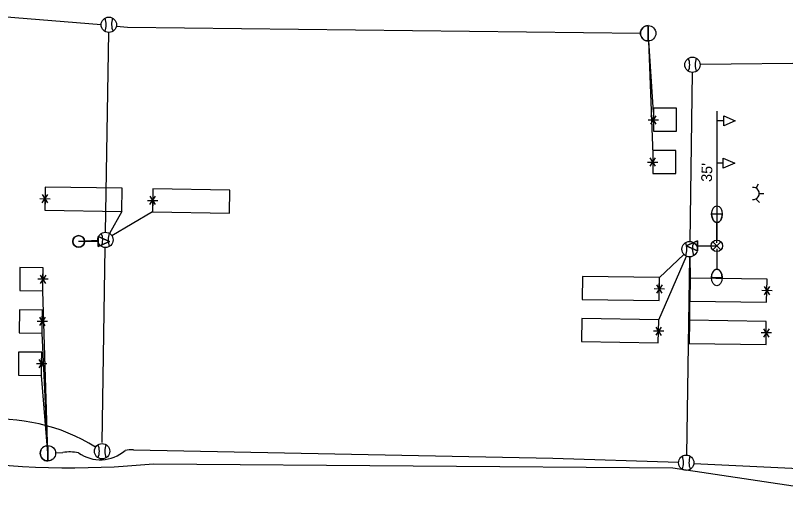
# Model space of a CAD drawing. Extents: x 596176 to 605330, y 332416 to 402398.
# Drawn here: x 602723.5 to 602923.8, y 366066.6 to 366192.6 of the extents above; entities that cross this region are included whole.
import ezdxf

# ---------------------------------------------------------------- set-up
doc = ezdxf.new("R2010")
doc.units = 0
for name, color, linetype in [('P_LTG', 7, 'Continuous'), ('P_SIG', 7, 'Continuous'), ('P_SIG_Bold', 7, 'Continuous'), ('P_SIG_Conduit', 7, 'Continuous'), ('P_SIG_IC', 7, 'Continuous'), ('P_SIG_Loops', 7, 'Continuous')]:
    doc.layers.add(name, color=color, linetype=linetype)

# ---------------------------------------------------------------- blocks, each defined once
blk = doc.blocks.new('_U303')
at = {"layer": 'P_LTG'}
for p, q in [((4.32, 25.12), (-4.14, 25.12)), ((0.05, 2.3), (0.05, 18.44))]:
    blk.add_line(p, q, dxfattribs=at)
blk.add_ellipse((0.09, 25.12), major_axis=(0, 6.65), ratio=0.636439, dxfattribs=at)
blk.add_ellipse((0.09, 25.12), major_axis=(0, 6.65), ratio=0.636439, start_param=1.570796, end_param=4.712389, dxfattribs=at)

msp = doc.modelspace()

# ---------------------------------------------------------------- linework, layer by layer
at = {"layer": 'P_SIG'}
for p, q in [((602888.02, 366189.97), (602888, 366185.97)), ((602907.65, 366165.18), (602905.88, 366165.18)), ((602907.56, 366154.18), (602905.79, 366154.18)), ((602916.08, 366147.68), (602916.68, 366148.76)), ((602916.05, 366144.89), (602916.93, 366143.9)), ((602916.9, 366146.31), (602918.13, 366146.31)), ((602744.98, 366133.79), (602739.92, 366133.8)), ((602900.82, 366132.69), (602905.88, 366132.67)), ((602731.95, 366080.67), (602731.93, 366076.67))]:
    msp.add_line(p, q, dxfattribs=at)
for points in [[(602888, 366185.97), (602888.02, 366189.97)], [(602747.94, 366133.79), (602744.98, 366132.47), (602744.98, 366135.11), (602747.94, 366133.79)], [(602744.98, 366132.47), (602747.94, 366133.79), (602744.98, 366135.11), (602744.98, 366132.47)], [(602897.86, 366132.69), (602900.82, 366134), (602900.82, 366131.37), (602897.86, 366132.69)], [(602897.86, 366132.69), (602900.82, 366134), (602900.82, 366131.37), (602897.86, 366132.69)], [(602900.82, 366134), (602897.86, 366132.69), (602900.82, 366131.37), (602900.82, 366134)], [(602731.93, 366076.67), (602731.95, 366080.67)]]:
    msp.add_lwpolyline(points, dxfattribs=at)
for points in [[(602910.61, 366165.18), (602907.65, 366163.86), (602907.65, 366166.49)], [(602910.52, 366154.18), (602907.56, 366152.86), (602907.56, 366155.49)]]:
    msp.add_lwpolyline(points, close=True, dxfattribs=at)
for centre, radius in [((602747.78, 366190.19), 2), ((602888.01, 366187.97), 2), ((602899.53, 366179.78), 2), ((602739.92, 366133.8), 1.52), ((602739.92, 366133.8), 1.52), ((602739.92, 366133.8), 1.52), ((602746.89, 366134.2), 2), ((602898.79, 366131.79), 2), ((602731.94, 366078.67), 2), ((602746.02, 366079.2), 2), ((602897.91, 366076.21), 2)]:
    msp.add_circle(centre, radius, dxfattribs=at)
for centre, radius, start, end in [((602742.71, 366190.22), 4.36, 336.6741, 22.5272), ((602752.85, 366190.23), 4.36, 157.5751, 203.4282), ((602888.01, 366187.97), 2, 89.7008, 180), ((602888.01, 366187.97), 2, 180, 269.7008), ((602894.46, 366179.82), 4.36, 336.6741, 22.5272), ((602904.6, 366179.83), 4.36, 157.5751, 203.4282), ((602915.32, 366146.3), 1.58, 262.2462, 97.7538), ((602739.92, 366133.8), 1.52, 0, 180), ((602741.82, 366134.23), 4.36, 336.6741, 22.5272), ((602751.96, 366134.24), 4.36, 157.5751, 203.4282), ((602739.92, 366133.8), 1.52, 180, 0), ((602893.72, 366131.82), 4.36, 336.6741, 22.5272), ((602903.86, 366131.83), 4.36, 157.5751, 203.4282), ((602731.94, 366078.67), 2, 89.7008, 180), ((602740.95, 366079.24), 4.36, 336.6741, 22.5272), ((602751.09, 366079.25), 4.36, 157.5751, 203.4282), ((602731.94, 366078.67), 2, 180, 269.7008), ((602892.84, 366076.24), 4.36, 336.6741, 22.5272), ((602902.98, 366076.25), 4.36, 157.5751, 203.4282)]:
    msp.add_arc(centre, radius, start, end, dxfattribs=at)
at = {"layer": 'P_SIG_Bold'}
for p, q in [((602905.88, 366167.67), (602905.88, 366134.17)), ((602906.94, 366133.73), (602904.82, 366131.61)), ((602906.94, 366131.61), (602904.82, 366133.73))]:
    msp.add_line(p, q, dxfattribs=at)
msp.add_circle((602905.88, 366132.67), 1.5, dxfattribs=at)
at = {"layer": 'P_SIG_Conduit'}
for points in [[(602716.8, 366192.63), (602745.78, 366190.29)], [(602749.75, 366189.85), (602752.6, 366189.61), (602886.01, 366187.99)], [(602746.92, 366136.2), (602747.75, 366188.19)], [(602933.66, 366180.19), (602901.53, 366179.86)], [(602899.5, 366177.78), (602898.82, 366133.79)], [(602744.89, 366134.08), (602739.92, 366133.8)], [(602900.54, 366132.76), (602904.38, 366132.7)], [(602746.05, 366081.47), (602746.86, 366132.2)], [(602898.76, 366129.79), (602897.95, 366078.21)], [(602733.93, 366078.78), (602735.81, 366078.89)], [(602754.18, 366079.57), (602863.21, 366077.42), (602895.91, 366076.36)], [(602899.9, 366076.04), (602939.94, 366074.13)]]:
    msp.add_lwpolyline(points, dxfattribs=at)
for centre, radius, start, end in [((602719.11, 366039.94), 47.57, 57.9898, 96.3464), ((602737.54, 366066.77), 12.24, 79.0079, 98.1332), ((602745.55, 366086.8), 9.81, 234.6782, 311.0231), ((602753.8, 366070.72), 8.86, 87.5297, 101.8044)]:
    msp.add_arc(centre, radius, start, end, dxfattribs=at)
at = {"layer": 'P_SIG_IC'}
msp.add_lwpolyline([(602759.42, 366075.93), (602894.42, 366074.85), (602949.47, 366066.61)], dxfattribs=at)
msp.add_arc((602737.84, 366297.84), 222.95, 261.5069, 275.5534, dxfattribs=at)
at = {"layer": 'P_SIG_Loops'}
for p, q in [((602888.09, 366185.97), (602889.19, 366156.46)), ((602889.39, 366167.46), (602888.15, 366185.97)), ((602888.67, 366164.35), (602890.07, 366166.53)), ((602890.12, 366164.36), (602888.69, 366166.54)), ((602888.01, 366165.44), (602890.69, 366165.44)), ((602889.39, 366165.46), (602889.39, 366162.46)), ((602887.86, 366154.44), (602890.53, 366154.44)), ((602888.51, 366153.35), (602889.92, 366155.53)), ((602889.96, 366153.36), (602888.53, 366155.54)), ((602889.23, 366154.46), (602889.23, 366151.46)), ((602729.83, 366144.95), (602732.5, 366144.9)), ((602730.46, 366143.85), (602731.9, 366146)), ((602731.92, 366143.84), (602730.52, 366146.03)), ((602731.2, 366144.94), (602731.15, 366141.94)), ((602757.82, 366144.5), (602760.5, 366144.46)), ((602758.46, 366143.41), (602759.9, 366145.56)), ((602759.91, 366143.39), (602758.52, 366145.59)), ((602759.2, 366144.5), (602759.15, 366141.5)), ((602751.15, 366141.63), (602747.93, 366135.9)), ((602759.15, 366141.5), (602748.59, 366135.26)), ((602890.93, 366124.42), (602897.33, 366130.42)), ((602890.75, 366113.42), (602897.99, 366129.96)), ((602898.78, 366129.79), (602898.75, 366113.28)), ((602898.82, 366129.79), (602898.92, 366124.28)), ((602730.64, 366123.95), (602730.67, 366126.95)), ((602729.92, 366125.05), (602731.33, 366122.86)), ((602731.38, 366125.05), (602729.95, 366122.89)), ((602890.88, 366121.42), (602890.93, 366124.42)), ((602732.02, 366123.95), (602729.34, 366123.98)), ((602890.16, 366122.53), (602891.56, 366120.33)), ((602891.62, 366122.52), (602890.18, 366120.37)), ((602918.88, 366120.99), (602918.92, 366123.99)), ((602731.94, 366078.67), (602730.61, 366120.95)), ((602892.25, 366121.42), (602889.58, 366121.46)), ((602920.25, 366120.98), (602917.57, 366121.02)), ((602918.16, 366122.09), (602919.56, 366119.9)), ((602919.61, 366122.08), (602918.17, 366119.93)), ((602730.47, 366112.95), (602730.5, 366115.95)), ((602731.84, 366112.96), (602729.16, 366112.98)), ((602729.75, 366114.05), (602731.16, 366111.86)), ((602731.2, 366114.05), (602729.77, 366111.89)), ((602890.71, 366110.42), (602890.75, 366113.42)), ((602918.7, 366109.99), (602918.74, 366112.99)), ((602892.08, 366110.42), (602889.4, 366110.46)), ((602889.99, 366111.53), (602891.39, 366109.33)), ((602891.44, 366111.52), (602890, 366109.37)), ((602917.98, 366111.09), (602919.38, 366108.9)), ((602919.44, 366111.08), (602918, 366108.93)), ((602731.94, 366078.67), (602730.42, 366109.95)), ((602920.07, 366109.98), (602917.4, 366110.02)), ((602730.3, 366101.95), (602730.32, 366104.95)), ((602729.57, 366103.05), (602730.98, 366100.87)), ((602731.03, 366103.05), (602729.6, 366100.89)), ((602731.67, 366101.96), (602728.99, 366101.98)), ((602731.94, 366078.67), (602730.27, 366098.95))]:
    msp.add_line(p, q, dxfattribs=at)
for points in [[(602889.39, 366162.46), (602895.39, 366162.46), (602895.39, 366168.46), (602889.39, 366168.46)], [(602889.23, 366151.46), (602895.23, 366151.46), (602895.23, 366157.46), (602889.23, 366157.46)], [(602731.15, 366141.94), (602751.15, 366141.63), (602751.25, 366147.63), (602731.25, 366147.94)], [(602759.15, 366141.5), (602779.15, 366141.18), (602779.24, 366147.18), (602759.24, 366147.5)], [(602730.67, 366126.95), (602724.67, 366127.01), (602724.62, 366121.01), (602730.61, 366120.95)], [(602890.93, 366124.42), (602870.93, 366124.72), (602870.84, 366118.72), (602890.84, 366118.42)], [(602918.92, 366123.99), (602898.92, 366124.28), (602898.83, 366118.28), (602918.83, 366117.99)], [(602730.5, 366115.95), (602724.5, 366116.01), (602724.44, 366110.01), (602730.44, 366109.95)], [(602890.75, 366113.42), (602870.75, 366113.72), (602870.67, 366107.72), (602890.66, 366107.43)], [(602918.74, 366112.99), (602898.75, 366113.28), (602898.66, 366107.28), (602918.66, 366106.99)], [(602730.32, 366104.95), (602724.32, 366105.01), (602724.27, 366099.01), (602730.27, 366098.95)]]:
    msp.add_lwpolyline(points, close=True, dxfattribs=at)

# ---------------------------------------------------------------- block references
at = {"layer": 'P_LTG', "xscale": 0.32808333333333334, "yscale": 0.32808333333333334}
msp.add_blockref('_U303', (602905.88, 366132.67), dxfattribs=at)
at = {"layer": 'P_LTG', "xscale": 0.32808333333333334, "yscale": 0.32808333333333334, "rotation": 180}
msp.add_blockref('_U303', (602905.89, 366132.66), dxfattribs=at)

# ---------------------------------------------------------------- texts
at = {"layer": 'P_SIG_Bold'}
msp.add_text("35'", height=2.8, rotation=87.5418, dxfattribs=at).set_placement((602904.57, 366149.25))

doc.saveas('drawing.dxf')
